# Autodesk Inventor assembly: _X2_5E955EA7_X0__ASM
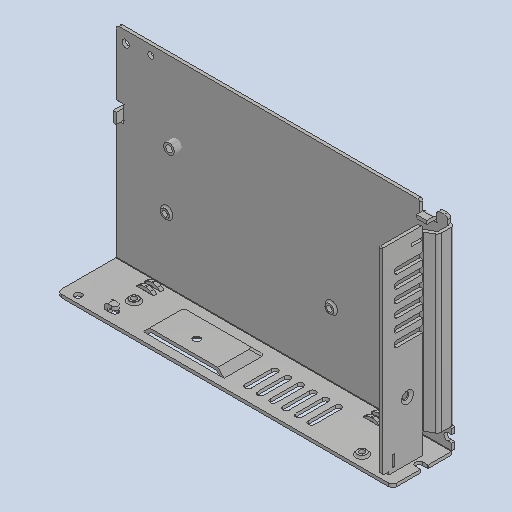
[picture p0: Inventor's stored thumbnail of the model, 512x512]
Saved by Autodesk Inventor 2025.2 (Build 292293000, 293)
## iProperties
Created: 2025-04
Part Number: _X2_5E955EA7_X0__ASM
Description: NOT SPECIFIED
Document SubType Name: Assembly
Designer: BennF
Author: BennF
Revision Number: 4LAST_VERSION
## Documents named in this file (4)
- C:\Users\BennF\Nextcloud\Benutzer\CNC JarBeRi\existing parts\Electronics\Powersupply LRS-150-24\LRS-150(230808)\LRS-150(230808)\_X2_5E955EA7_X0__ASM.iam
- C:\Users\BennF\Nextcloud\Benutzer\CNC JarBeRi\existing parts\Electronics\Powersupply LRS-150-24\LRS-150(230808)\LRS-150(230808)\DD.ipt
- C:\Users\BennF\Nextcloud\Benutzer\CNC JarBeRi\existing parts\Electronics\Powersupply LRS-150-24\LRS-150(230808)\LRS-150(230808)\TTTT.ipt
- C:\Users\BennF\Nextcloud\Benutzer\CNC JarBeRi\existing parts\Electronics\Powersupply LRS-150-24\LRS-150(230808)\LRS-150(230808)\DDD.ipt
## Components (3 placed, 3 different names)
1. DD_18
2. TTTT_19
3. DDD_20
